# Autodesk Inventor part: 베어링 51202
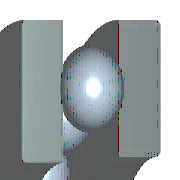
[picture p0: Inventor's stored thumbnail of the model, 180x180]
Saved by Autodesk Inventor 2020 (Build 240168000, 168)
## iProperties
Created: 2012-02
Part Number: 베어링 51202
Material: 강철, 연강
Description: 롤링 베어링 - 플랫 뒷면이 있는 스러스트 볼 베어링
Document SubType Name: Modeling
Standard: KS B 2022
Designer: mduedu
Standards Organization: KS
Language: ko-KR
Size Designation: 51202 - 15 x 32 x 12
Categories: <MemberInstance><Categories><Category DisplayName="샤프트 부품" InternalName="7f7aeb1f-a693-4053-b835-cee3144e0d98" Mnemonic="SHFT"><Category DisplayName="베어링" Inter
Density: 1 g/cm^3
Appearance: 진녹색
IsCustomPart: 1
Author: mduedu
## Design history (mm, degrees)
sketch "스케치1" dims "d3" = 5.28 (= 0.44 x KB)
  geometry: L1 (6, 9.61)-(6, 14.89); L2 (8.64, 12.25)-(3.36, 12.25); L3 (3.6, 16)-(0, 16); L4 (3.6, 7.5)-(0, 7.5); L5 (8.4, 13.35)-(8.4, 16); L6 (8.4, 16)-(12, 16); L7 (12, 16)-(12, 8.5); L8 (12, 8.5)-(8.4, 8.5); L9 (8.4, 8.5)-(8.4, 11.15); L10 (3.6, 16)-(3.6, 13.35); L11 (3.6, 11.15)-(3.6, 7.5); L12 (-1.8, 0)-(10.8, 0) reference; L13 (0, -0.022)-(0, 5.522) reference; 1 further point
  constraints: 22 end point, 5 perpendicular, 2 equal length, 2 midpoint, 2 parallel, 2 point on line, 1 collinear, 10 other
  dimensions: "d8" = 4.8 diameter of L11 L1 (= 0.4 x KB); "d11" = 15 diameter of L4 L12 (= WD); "d12" = 17 diameter of L8 L12 (= KAD1); "d13" = 32 diameter of L3 L12 (= KID1); "d14" = 32 diameter of L6 L12 (= BD); "d15" = 24.5 diameter of point (6, 12.25) L12 (= 0.5 x KID1 + 0.5 x KAD1); "d16" = 6 distance from line of point (6, 12.25) L13 (= 0.5 x KB); "d18" = 12 distance between parallel lines of L7 L13 (= KB)
revolve "본체" stored, may be unused: angle "d9" = 90 deg
revolve "볼" stored, may be unused: angle "d10" = 90 deg
pattern_circular "IDS_ARRAYBALL[SIMPL:T]" dims angle "d2" = 360 deg
body "Solid1"
fillet "모깎기1" dims "d4" = 0.6 (= KRS)
fillet "모깎기2" dims "d5" = 0.6 (= KRS)
other parameters: "WD" = 15 [user parameter; used in 2 equation terms], "KAD1" = 17 [user parameter; used in 3 equation terms], "KID1" = 32 [user parameter; used in 3 equation terms], "BD" = 32 [user parameter; used in 2 equation terms], "KB" = 12 [user parameter; used in 6 equation terms], "KRS" = 0.6 [user parameter; used in 2 equation terms], "d0" = 2.4 (= 0.2 x KB), "d6" = 0, "d7" = 0, "d19" = 0, "d41" = 0, "d42" = 0, "WR" = 7.5 (= 0.5 x WD) [user parameter], "BC" = 1.65e+07 [user parameter], "BBA" = 90 deg [user parameter], "BC0" = 2.7e+07 [user parameter], "BR" = 16 (= 0.5 x BD) [user parameter]
